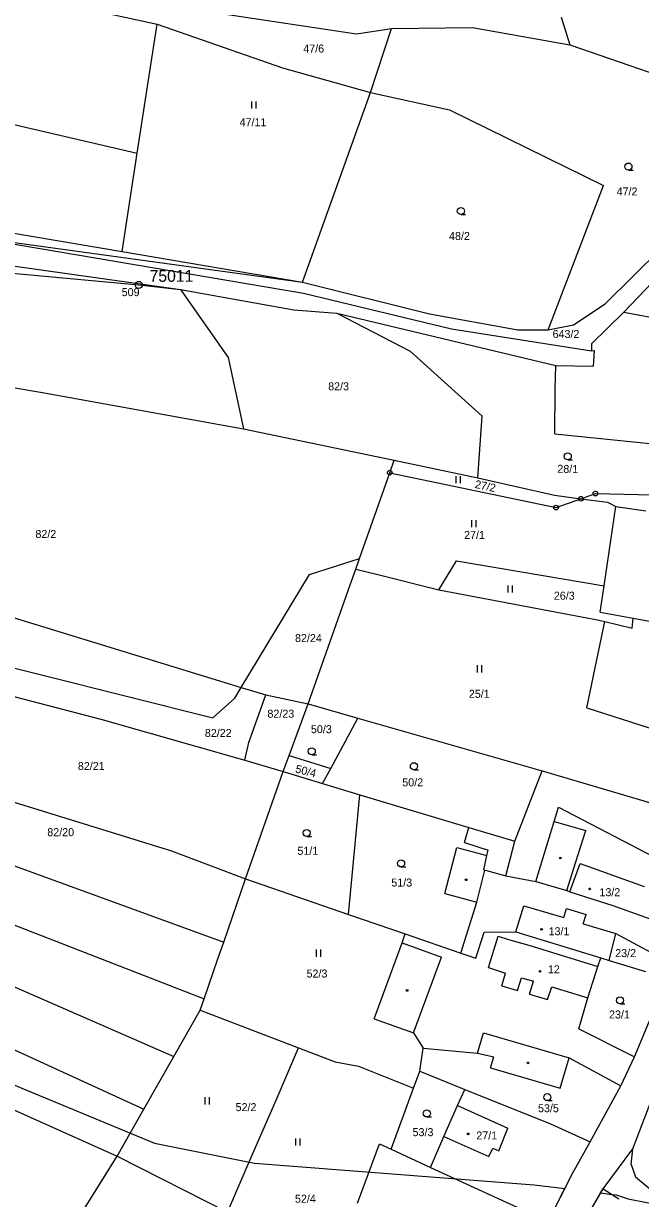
# Model space of a CAD drawing. Extents: x -743888 to -742027, y -1128394 to -1126768.
# Drawn here: x -743087.8 to -742956.8, y -1127574.7 to -1127325 of the extents above; entities that cross this region are included whole.
import ezdxf

# ---------------------------------------------------------------- set-up
doc = ezdxf.new("R2010")
doc.units = 0
for name, color, linetype in [('Vrstva 1', 7, 'Continuous'), ('Vrstva 17', 7, 'Continuous'), ('Vrstva 18', 7, 'Continuous'), ('Vrstva 19', 7, 'Continuous'), ('Vrstva 24', 7, 'Continuous'), ('Vrstva 25', 7, 'Continuous'), ('Vrstva 3', 7, 'Continuous'), ('Vrstva 37', 7, 'Continuous'), ('Vrstva 4', 7, 'Continuous'), ('Vrstva 52', 7, 'Continuous'), ('Vrstva 53', 7, 'Continuous'), ('Vrstva 6', 7, 'Continuous')]:
    doc.layers.add(name, color=color, linetype=linetype)

msp = doc.modelspace()

# ---------------------------------------------------------------- linework, layer by layer
at = {"layer": 'Vrstva 1'}
for p, q in [((-743010.06, -1127420.45), (-743009.13, -1127417.82)), ((-743016.5, -1127438.72), (-743010.06, -1127420.45)), ((-743010.06, -1127420.45), (-742974.74, -1127427.87)), ((-742975.09, -1127425.22), (-742969.45, -1127425.98)), ((-742974.74, -1127427.87), (-742969.45, -1127425.98)), ((-742969.45, -1127425.98), (-742966.36, -1127424.88)), ((-742969.45, -1127425.98), (-742963.79, -1127426.75)), ((-742966.36, -1127424.88), (-742929.36, -1127425.71))]:
    msp.add_line(p, q, dxfattribs=at)
for points in [[(-743048.7, -1127322.46), (-743017.08, -1127327.24)], [(-742973.63, -1127323.67), (-742971.84, -1127329.53)], [(-743017.08, -1127327.24), (-743009.69, -1127326.1)], [(-743014.16, -1127339.69), (-743009.69, -1127326.1)], [(-743009.69, -1127326.1), (-742992.5, -1127325.85)], [(-742992.5, -1127325.85), (-742971.84, -1127329.53)], [(-742971.84, -1127329.53), (-742954.93, -1127335.36)], [(-743028.55, -1127379.99), (-743014.16, -1127339.69)], [(-742976.38, -1127390.08), (-742964.65, -1127359.41)], [(-742964.3, -1127384.57), (-742946.62, -1127367.12)], [(-743147.34, -1127368.46), (-743054.48, -1127381.54)], [(-743100.68, -1127370.05), (-743028.55, -1127379.99)], [(-742960.31, -1127386.35), (-742945.39, -1127370.73)], [(-743054.48, -1127381.54), (-743044.4, -1127395.97)], [(-743054.48, -1127381.54), (-743030.41, -1127385.86)], [(-743028.55, -1127379.99), (-743001.6, -1127386.7)], [(-742971.06, -1127389.03), (-742964.3, -1127384.57)], [(-743030.41, -1127385.86), (-743021.3, -1127386.55)], [(-743021.3, -1127386.55), (-742974.81, -1127397.66)], [(-743001.6, -1127386.7), (-742982.84, -1127390.07)], [(-742967.2, -1127393.06), (-742960.31, -1127386.35)], [(-742960.31, -1127386.35), (-742951.24, -1127388.03)], [(-742976.38, -1127390.08), (-742971.06, -1127389.03)], [(-742982.84, -1127390.07), (-742976.38, -1127390.08)], [(-742967.2, -1127393.06), (-742967.2, -1127394.53)], [(-742967.2, -1127394.53), (-742966.54, -1127394.52)], [(-742966.76, -1127397.79), (-742966.54, -1127394.52)], [(-743044.4, -1127395.97), (-743041.1, -1127411.11)], [(-742974.95, -1127402.66), (-742974.81, -1127397.66)], [(-742974.81, -1127397.66), (-742966.76, -1127397.79)], [(-742975.01, -1127412.21), (-742974.95, -1127402.66)], [(-743041.1, -1127411.11), (-743009.13, -1127417.82)], [(-742975.01, -1127412.21), (-742949.94, -1127414.75)], [(-743009.13, -1127417.82), (-742991.33, -1127421.56)], [(-742991.33, -1127421.56), (-742975.09, -1127425.22)], [(-742963.79, -1127426.75), (-742962.06, -1127427.67)], [(-742964.54, -1127444.49), (-742962.06, -1127427.67)], [(-742962.06, -1127427.67), (-742955.66, -1127428.57)], [(-743017.29, -1127440.95), (-743016.5, -1127438.72)], [(-743018.47, -1127444.3), (-743017.29, -1127440.95)], [(-743017.29, -1127440.95), (-743012.61, -1127442.11)], [(-743012.61, -1127442.11), (-742999.6, -1127445.32)], [(-743027.39, -1127469.59), (-743018.47, -1127444.3)], [(-742965.34, -1127450.06), (-742964.54, -1127444.49)], [(-742999.6, -1127445.32), (-742965.61, -1127451.81)], [(-742965.61, -1127451.81), (-742964.4, -1127452.09)], [(-742965.34, -1127450.06), (-742958.39, -1127451.34)], [(-742958.39, -1127451.34), (-742942.2, -1127454.33)], [(-743031.43, -1127480.55), (-743027.39, -1127469.59)], [(-743027.39, -1127469.59), (-743016.81, -1127472.62)], [(-742968.23, -1127470.39), (-742947.25, -1127477.16)], [(-743022.6, -1127483.32), (-743016.81, -1127472.62)], [(-743016.81, -1127472.62), (-742977.71, -1127483.81)], [(-743032.69, -1127483.96), (-743031.43, -1127480.55)], [(-743040.66, -1127506.77), (-743032.69, -1127483.96)], [(-743032.69, -1127483.96), (-743024.31, -1127486.49)], [(-743024.31, -1127486.49), (-743022.6, -1127483.32)], [(-742983.49, -1127498.74), (-742977.71, -1127483.81)], [(-742977.71, -1127483.81), (-742954.21, -1127490.71)], [(-743024.31, -1127486.49), (-743016.42, -1127488.87)], [(-743016.42, -1127488.87), (-742993.26, -1127495.85)], [(-742975.14, -1127494.55), (-742974.21, -1127491.49)], [(-742974.21, -1127491.49), (-742943.52, -1127507.49)], [(-742979.03, -1127507.34), (-742975.14, -1127494.55)], [(-742993.26, -1127495.85), (-742983.49, -1127498.74)], [(-742985.43, -1127506.13), (-742983.49, -1127498.74)], [(-742998.35, -1127509.89), (-742995.84, -1127500.07)], [(-742995.84, -1127500.07), (-742989.41, -1127501.75)], [(-742990.08, -1127504.83), (-742989.41, -1127501.75)], [(-743045.31, -1127520.19), (-743040.66, -1127506.77)], [(-743040.66, -1127506.77), (-743018.83, -1127514.29)], [(-742990.08, -1127504.83), (-742989.89, -1127504.88)], [(-742989.89, -1127504.88), (-742989.51, -1127504.99)], [(-742989.51, -1127504.99), (-742985.43, -1127506.13)], [(-742985.43, -1127506.13), (-742979.03, -1127507.34)], [(-742979.03, -1127507.34), (-742972.41, -1127509.22)], [(-742972.41, -1127509.22), (-742971.81, -1127509.49)], [(-742971.81, -1127509.49), (-742962.69, -1127512.44)], [(-742998.35, -1127509.89), (-742991.56, -1127511.71)], [(-742994.94, -1127522.52), (-742991.56, -1127511.71)], [(-743018.83, -1127514.29), (-743006.77, -1127518.44)], [(-742962.69, -1127512.44), (-742949.22, -1127517.23)], [(-743007.45, -1127520.31), (-743006.77, -1127518.44)], [(-743006.77, -1127518.44), (-742994.94, -1127522.52)], [(-742991.77, -1127523.61), (-742989.99, -1127518.04)], [(-742983.25, -1127518.03), (-742965.23, -1127523.55)], [(-742963.44, -1127524.1), (-742962.06, -1127518.33)], [(-742962.06, -1127518.33), (-742949.93, -1127524.86)], [(-743046.55, -1127523.76), (-743045.31, -1127520.19)], [(-743013.35, -1127536.47), (-743007.45, -1127520.31)], [(-743049.5, -1127532.27), (-743046.55, -1127523.76)], [(-742994.94, -1127522.52), (-742991.77, -1127523.61)], [(-742965.83, -1127525.39), (-742965.23, -1127523.55)], [(-742965.23, -1127523.55), (-742963.44, -1127524.1)], [(-742968.01, -1127532.03), (-742965.83, -1127525.39)], [(-742969.92, -1127538.58), (-742968.01, -1127532.03)], [(-742958.07, -1127544.59), (-742952.01, -1127529.96)], [(-743050.32, -1127534.62), (-743049.5, -1127532.27)], [(-743055.93, -1127544.5), (-743050.32, -1127534.62)], [(-743050.32, -1127534.62), (-743029.41, -1127542.64)], [(-743013.35, -1127536.47), (-743005, -1127539.46)], [(-743005, -1127539.46), (-743002.99, -1127542.69)], [(-742969.92, -1127538.58), (-742958.07, -1127544.59)], [(-743062.27, -1127555.66), (-743055.93, -1127544.5)], [(-743034.2, -1127553.73), (-743029.41, -1127542.64)], [(-743029.41, -1127542.64), (-743021.68, -1127545.63)], [(-743003.69, -1127547.61), (-743002.99, -1127542.69)], [(-743002.99, -1127542.69), (-742991.4, -1127543.81)], [(-742991.4, -1127543.81), (-742987.95, -1127544.57)], [(-743021.68, -1127545.63), (-743016.66, -1127546.56)], [(-743016.66, -1127546.56), (-743005.01, -1127551.2)], [(-742988.63, -1127546.87), (-742987.95, -1127544.57)], [(-742988.63, -1127546.87), (-742973.89, -1127551.23)], [(-742973.89, -1127551.23), (-742971.94, -1127544.76)], [(-742971.94, -1127544.76), (-742960.97, -1127550.69)], [(-742960.97, -1127550.69), (-742958.07, -1127544.59)], [(-743005.01, -1127551.2), (-743003.69, -1127547.61)], [(-743003.69, -1127547.61), (-742994.1, -1127551.47)], [(-743009.74, -1127564.2), (-743005.01, -1127551.2)], [(-742995.64, -1127554.9), (-742994.1, -1127551.47)], [(-742994.1, -1127551.47), (-742975.9, -1127558.78)], [(-742967.51, -1127562.65), (-742960.97, -1127550.69)], [(-743039.4, -1127565.75), (-743034.2, -1127553.73)], [(-742958.43, -1127564.08), (-742954.72, -1127554.49)], [(-743067.95, -1127565.66), (-743062.27, -1127555.66)], [(-742998.58, -1127561.51), (-742995.64, -1127554.9)], [(-742975.9, -1127558.78), (-742967.51, -1127562.65)], [(-743001.38, -1127568.05), (-742998.58, -1127561.51)], [(-743016.9, -1127575.68), (-743012.24, -1127563.05)], [(-743012.24, -1127563.05), (-743009.74, -1127564.2)], [(-743009.74, -1127564.2), (-743001.38, -1127568.05)], [(-742971.19, -1127569.17), (-742967.51, -1127562.65)], [(-742964.75, -1127572.6), (-742958.43, -1127564.08)], [(-742958.76, -1127567.42), (-742958.43, -1127564.08)], [(-743072.64, -1127573.17), (-743067.95, -1127565.66)], [(-743067.95, -1127565.66), (-743044.5, -1127577.53)], [(-743044.5, -1127577.53), (-743039.4, -1127565.75)], [(-743001.38, -1127568.05), (-742979.47, -1127578.16)], [(-742976.43, -1127579.56), (-742971.19, -1127569.17)], [(-742958.76, -1127567.42), (-742957.84, -1127570.04)], [(-742957.84, -1127570.04), (-742953.72, -1127573.43)], [(-743082.43, -1127588.87), (-743072.64, -1127573.17)], [(-742970.21, -1127581.92), (-742964.75, -1127572.6)], [(-742964.75, -1127572.6), (-742961.39, -1127574.71)]]:
    msp.add_lwpolyline(points, dxfattribs=at)
at = {"layer": 'Vrstva 24'}
for p, q in [((-743063.41, -1127380.56), (-743063.31, -1127380.56)), ((-743010.11, -1127420.45), (-743010.01, -1127420.45)), ((-742969.5, -1127425.98), (-742969.4, -1127425.98)), ((-742966.41, -1127424.88), (-742966.31, -1127424.88)), ((-742974.79, -1127427.87), (-742974.69, -1127427.87))]:
    msp.add_line(p, q, dxfattribs=at)
for centre, radius in [((-743063.36, -1127380.56), 0.756), ((-743010.06, -1127420.45), 0.499), ((-742966.36, -1127424.88), 0.499), ((-742969.45, -1127425.98), 0.499), ((-742974.74, -1127427.87), 0.499)]:
    msp.add_circle(centre, radius, dxfattribs=at)
at = {"layer": 'Vrstva 25'}
for p, q in [((-743039.43, -1127341.57), (-743039.43, -1127343.07)), ((-743038.43, -1127343.07), (-743038.43, -1127341.57)), ((-742959.36, -1127356.16), (-742958.36, -1127356.16)), ((-742994.95, -1127365.62), (-742993.95, -1127365.62)), ((-742972.24, -1127417.73), (-742971.24, -1127417.73)), ((-742996, -1127421.2), (-742996, -1127422.7)), ((-742995, -1127422.7), (-742995, -1127421.2)), ((-742992.72, -1127430.55), (-742992.72, -1127432.05)), ((-742991.72, -1127432.05), (-742991.72, -1127430.55)), ((-742984.95, -1127444.4), (-742984.95, -1127445.9)), ((-742983.95, -1127445.9), (-742983.95, -1127444.4)), ((-742991.51, -1127461.38), (-742991.51, -1127462.88)), ((-742990.51, -1127462.88), (-742990.51, -1127461.38)), ((-743026.61, -1127480.4), (-743025.61, -1127480.4)), ((-743004.92, -1127483.57), (-743003.92, -1127483.57)), ((-743027.69, -1127497.75), (-743026.69, -1127497.75)), ((-743007.64, -1127504.22), (-743006.64, -1127504.22)), ((-743025.67, -1127521.78), (-743025.67, -1127523.28)), ((-743024.67, -1127523.28), (-743024.67, -1127521.78)), ((-742961.15, -1127533.31), (-742960.15, -1127533.31)), ((-743049.36, -1127553.15), (-743049.36, -1127554.65)), ((-743048.36, -1127554.65), (-743048.36, -1127553.15)), ((-742976.58, -1127553.86), (-742975.58, -1127553.86)), ((-743002.18, -1127557.34), (-743001.18, -1127557.34)), ((-743030.06, -1127561.93), (-743030.06, -1127563.43)), ((-743029.06, -1127563.43), (-743029.06, -1127561.93))]:
    msp.add_line(p, q, dxfattribs=at)
for centre, radius in [((-742959.36, -1127355.41), 0.75), ((-742994.95, -1127364.87), 0.75), ((-742972.24, -1127416.98), 0.75), ((-743026.61, -1127479.65), 0.75), ((-743004.92, -1127482.82), 0.75), ((-743027.69, -1127497), 0.75), ((-743007.64, -1127503.47), 0.75), ((-742973.84, -1127502.33), 0.175), ((-742993.83, -1127506.94), 0.175), ((-742967.6, -1127508.88), 0.175), ((-742977.81, -1127517.48), 0.175), ((-742978.13, -1127526.39), 0.175), ((-743006.37, -1127530.46), 0.175), ((-742961.15, -1127532.56), 0.75), ((-742980.7, -1127545.84), 0.175), ((-742976.58, -1127553.11), 0.75), ((-743002.18, -1127556.59), 0.75), ((-742993.39, -1127560.92), 0.175)]:
    msp.add_circle(centre, radius, dxfattribs=at)
at = {"layer": 'Vrstva 3'}
for points in [[(-742971.81, -1127509.49), (-742969.62, -1127503.47)], [(-742969.62, -1127503.47), (-742956.03, -1127508.38)], [(-742971.81, -1127509.49), (-742962.69, -1127512.44)], [(-742983.25, -1127518.03), (-742981.6, -1127512.47)], [(-742981.6, -1127512.47), (-742973.1, -1127514.99)], [(-742973.1, -1127514.99), (-742972.53, -1127513.06)], [(-742972.53, -1127513.06), (-742968.35, -1127514.3)], [(-742968.94, -1127516.27), (-742968.35, -1127514.3)], [(-742962.69, -1127512.44), (-742949.22, -1127517.23)], [(-742968.94, -1127516.27), (-742962.06, -1127518.33)], [(-742989.07, -1127525.61), (-742987.02, -1127518.91)], [(-742987.02, -1127518.91), (-742984.85, -1127519.61)], [(-742983.25, -1127518.03), (-742965.23, -1127523.55)], [(-742963.44, -1127524.1), (-742962.06, -1127518.33)], [(-742984.85, -1127519.61), (-742980.49, -1127520.84)], [(-742980.49, -1127520.84), (-742965.83, -1127525.39)], [(-742965.23, -1127523.55), (-742963.44, -1127524.1)], [(-742989.07, -1127525.61), (-742985.46, -1127526.79)], [(-742986.28, -1127529.44), (-742985.46, -1127526.79)], [(-742968.01, -1127532.03), (-742965.83, -1127525.39)], [(-742986.28, -1127529.44), (-742982.9, -1127530.47)], [(-742982.9, -1127530.47), (-742982.08, -1127527.77)], [(-742982.08, -1127527.77), (-742979.51, -1127528.51)], [(-742980.35, -1127531.26), (-742979.51, -1127528.51)], [(-742980.35, -1127531.26), (-742976.56, -1127532.4)], [(-742976.56, -1127532.4), (-742975.66, -1127529.7)], [(-742975.66, -1127529.7), (-742968.01, -1127532.03)], [(-742998.58, -1127561.51), (-742995.64, -1127554.9)], [(-742995.64, -1127554.9), (-742984.94, -1127559.69)], [(-742998.58, -1127561.51), (-742988.98, -1127565.74)], [(-742986.89, -1127564.52), (-742984.94, -1127559.69)], [(-742988.98, -1127565.74), (-742988.19, -1127563.94)], [(-742988.19, -1127563.94), (-742986.89, -1127564.52)]]:
    msp.add_lwpolyline(points, dxfattribs=at)
at = {"layer": 'Vrstva 37'}
for centre in [(-742967.6, -1127508.88), (-742977.81, -1127517.48), (-742978.13, -1127526.39), (-742993.39, -1127560.92)]:
    msp.add_circle(centre, 0.175, dxfattribs=at)
at = {"layer": 'Vrstva 4'}
for points in [[(-742975.14, -1127494.55), (-742968.39, -1127496.47)], [(-742994.2, -1127499.03), (-742993.26, -1127495.85)], [(-742970.5, -1127503.16), (-742968.39, -1127496.47)], [(-742994.2, -1127499.03), (-742989.17, -1127500.66)], [(-742989.41, -1127501.75), (-742989.17, -1127500.66)], [(-742972.41, -1127509.22), (-742970.5, -1127503.16)], [(-742971.81, -1127509.49), (-742969.62, -1127503.47)], [(-742969.62, -1127503.47), (-742956.03, -1127508.38)], [(-742991.56, -1127511.71), (-742989.89, -1127504.88)], [(-742983.25, -1127518.03), (-742981.6, -1127512.47)], [(-742981.6, -1127512.47), (-742973.1, -1127514.99)], [(-742973.1, -1127514.99), (-742972.53, -1127513.06)], [(-742972.53, -1127513.06), (-742968.35, -1127514.3)], [(-742968.94, -1127516.27), (-742968.35, -1127514.3)], [(-742968.94, -1127516.27), (-742962.06, -1127518.33)], [(-742989.07, -1127525.61), (-742987.02, -1127518.91)], [(-742987.02, -1127518.91), (-742984.85, -1127519.61)], [(-743007.45, -1127520.31), (-742999.03, -1127523.38)], [(-742984.85, -1127519.61), (-742980.49, -1127520.84)], [(-742980.49, -1127520.84), (-742965.83, -1127525.39)], [(-743005, -1127539.46), (-742999.03, -1127523.38)], [(-742989.07, -1127525.61), (-742985.46, -1127526.79)], [(-742986.28, -1127529.44), (-742985.46, -1127526.79)], [(-742986.28, -1127529.44), (-742982.9, -1127530.47)], [(-742982.9, -1127530.47), (-742982.08, -1127527.77)], [(-742982.08, -1127527.77), (-742979.51, -1127528.51)], [(-742980.35, -1127531.26), (-742979.51, -1127528.51)], [(-742980.35, -1127531.26), (-742976.56, -1127532.4)], [(-742976.56, -1127532.4), (-742975.66, -1127529.7)], [(-742975.66, -1127529.7), (-742968.01, -1127532.03)], [(-742991.4, -1127543.81), (-742990.15, -1127539.46)], [(-742990.15, -1127539.46), (-742971.94, -1127544.76)], [(-742995.64, -1127554.9), (-742984.94, -1127559.69)], [(-742998.58, -1127561.51), (-742988.98, -1127565.74)], [(-742986.89, -1127564.52), (-742984.94, -1127559.69)], [(-742988.98, -1127565.74), (-742988.19, -1127563.94)], [(-742988.19, -1127563.94), (-742986.89, -1127564.52)]]:
    msp.add_lwpolyline(points, dxfattribs=at)
at = {"layer": 'Vrstva 52'}
for points in [[(-742972.89, -1127572.54), (-742971.19, -1127569.17), (-742967.51, -1127562.65), (-742960.97, -1127550.69), (-742958.07, -1127544.59), (-742952.01, -1127529.96), (-742951.87, -1127529.63), (-742949.93, -1127524.86), (-742947.48, -1127518.45), (-742943.52, -1127507.49), (-742939.27, -1127495.28), (-742928.77, -1127471.57), (-742930.03, -1127470.75), (-742926.01, -1127462.54), (-742919.56, -1127450.77), (-742911.88, -1127437.64), (-742907.65, -1127433.29), (-742900.6, -1127419.3), (-742892.14, -1127404.73), (-742890.15, -1127399.92)], [(-742965.26, -1127573.48), (-742964.75, -1127572.6), (-742958.43, -1127564.08), (-742954.72, -1127554.49), (-742950.97, -1127547.61), (-742944.28, -1127528.98), (-742929.86, -1127490.53), (-742926.08, -1127481.57), (-742925.07, -1127479.17), (-742918.99, -1127466.07), (-742914.39, -1127456.16), (-742910.36, -1127448.54), (-742907.43, -1127444.81), (-742902.44, -1127441.06), (-742891.64, -1127420.53), (-742883.68, -1127406.25)], [(-743096.94, -1127547.63), (-743060, -1127562.88), (-743038.81, -1127567.13), (-742979.38, -1127571.75), (-742972.89, -1127572.54)], [(-743014.19, -1127643.46), (-743006.21, -1127631.58), (-743002.72, -1127626.56), (-742999.93, -1127620.98), (-743000.05, -1127620.45), (-742996.62, -1127614.4), (-742993.07, -1127607.9), (-742991.6, -1127605.04), (-742983.9, -1127588.07), (-742980.12, -1127580.33), (-742979.47, -1127578.16), (-742976.43, -1127579.56), (-742972.89, -1127572.54)], [(-742999.9, -1127643.94), (-742990.11, -1127623.65), (-742984.29, -1127611.5), (-742984.97, -1127610.98), (-742978.95, -1127598.97), (-742974.2, -1127589.77), (-742973.05, -1127587.2), (-742970.21, -1127581.92), (-742965.26, -1127573.48)], [(-742965.26, -1127573.48), (-742962.89, -1127573.77), (-742962, -1127573.88), (-742959.44, -1127574.75), (-742946.43, -1127577.24), (-742935.31, -1127579.38), (-742933.19, -1127580.25), (-742923.81, -1127581.5), (-742895, -1127588.25), (-742870.38, -1127595.5), (-742826.25, -1127613.38), (-742782.56, -1127629.88), (-742777.06, -1127632.88), (-742760.94, -1127638.75), (-742741, -1127643.5)]]:
    msp.add_lwpolyline(points, dxfattribs=at)
at = {"layer": 'Vrstva 6'}
for points in [[(-743086.21, -1127319.28), (-743059.46, -1127325.17)], [(-743063.68, -1127352.59), (-743059.46, -1127325.17)], [(-743059.46, -1127325.17), (-743032.86, -1127334.46)], [(-743140.7, -1127334.62), (-743063.68, -1127352.59)], [(-743032.86, -1127334.46), (-743014.16, -1127339.69)], [(-743014.16, -1127339.69), (-742997.35, -1127343.38)], [(-742997.35, -1127343.38), (-742964.65, -1127359.41)], [(-743066.9, -1127373.47), (-743063.68, -1127352.59)], [(-743161.95, -1127357.36), (-743066.9, -1127373.47)], [(-743100.68, -1127370.05), (-743028.35, -1127382.31)], [(-743066.9, -1127373.47), (-743028.55, -1127379.99)], [(-743112.56, -1127376.02), (-743063.36, -1127380.56)], [(-743063.36, -1127380.56), (-743054.48, -1127381.54)], [(-743028.35, -1127382.31), (-742996.94, -1127389.89)], [(-743021.3, -1127386.55), (-743005.74, -1127394.62)], [(-743167.67, -1127389.27), (-743084.2, -1127403.32)], [(-742996.94, -1127389.89), (-742967.2, -1127394.53)], [(-743005.74, -1127394.62), (-742990.42, -1127408.45)], [(-743084.2, -1127403.32), (-743041.1, -1127411.11)], [(-742991.33, -1127421.56), (-742990.42, -1127408.45)], [(-743027.12, -1127442.06), (-743016.5, -1127438.72)], [(-742999.6, -1127445.32), (-742995.91, -1127439.17)], [(-742995.91, -1127439.17), (-742964.54, -1127444.49)], [(-743041.59, -1127466.09), (-743027.12, -1127442.06)], [(-743108.99, -1127445.38), (-743041.59, -1127466.09)], [(-743155.92, -1127450.8), (-743071.4, -1127472.85)], [(-742968.23, -1127470.39), (-742964.4, -1127452.09)], [(-742964.4, -1127452.09), (-742958.54, -1127453.46)], [(-742958.54, -1127453.46), (-742958.39, -1127451.34)], [(-743119.92, -1127454.41), (-743047.66, -1127472.53)], [(-743042.97, -1127468.39), (-743041.59, -1127466.09)], [(-743041.59, -1127466.09), (-743036.38, -1127467.62)], [(-743047.66, -1127472.53), (-743042.97, -1127468.39)], [(-743039.98, -1127477.77), (-743036.38, -1127467.62)], [(-743036.38, -1127467.62), (-743027.39, -1127469.59)], [(-743071.4, -1127472.85), (-743040.81, -1127481.55)], [(-743133.85, -1127476.88), (-743056.44, -1127500.82)], [(-743040.81, -1127481.55), (-743039.98, -1127477.77)], [(-743040.81, -1127481.55), (-743032.69, -1127483.96)], [(-743031.43, -1127480.55), (-743022.6, -1127483.32)], [(-743018.83, -1127514.29), (-743016.42, -1127488.87)], [(-743155.28, -1127491.09), (-743049.5, -1127532.27)], [(-743164.36, -1127497.11), (-743055.93, -1127544.5)], [(-743104.96, -1127498.48), (-743045.31, -1127520.19)], [(-743056.44, -1127500.82), (-743040.66, -1127506.77)], [(-743157.93, -1127511.82), (-743062.27, -1127555.66)], [(-742989.99, -1127518.04), (-742983.25, -1127518.03)], [(-742963.44, -1127524.1), (-742955.76, -1127526.44)], [(-743113.85, -1127545.15), (-743067.95, -1127565.66)]]:
    msp.add_lwpolyline(points, dxfattribs=at)

# ---------------------------------------------------------------- texts
at = {"layer": 'Vrstva 17'}
msp.add_text('509', height=1.7, dxfattribs=at).set_placement((-743066.98, -1127382.94))
at = {"layer": 'Vrstva 18'}
for s, p in [('47/6', (-743028.42, -1127331.2)), ('47/11', (-743041.94, -1127346.84)), ('47/2', (-742961.87, -1127361.56)), ('48/2', (-742997.46, -1127371.02)), ('643/2', (-742975.47, -1127391.84)), ('82/3', (-743023.13, -1127402.95)), ('82/2', (-743085.3, -1127434.33)), ('27/1', (-742994.26, -1127434.53)), ('26/3', (-742975.2, -1127447.44)), ('82/24', (-743030.17, -1127456.44)), ('25/1', (-742993.25, -1127468.28)), ('82/23', (-743036.03, -1127472.51)), ('50/3', (-743026.79, -1127475.8)), ('82/22', (-743049.32, -1127476.6)), ('82/21', (-743076.29, -1127483.62)), ('50/2', (-743007.39, -1127487.09)), ('82/20', (-743082.78, -1127497.68)), ('51/1', (-743029.66, -1127501.64)), ('51/3', (-743009.72, -1127508.38)), ('23/2', (-742962.17, -1127523.36)), ('52/3', (-743027.72, -1127527.71)), ('23/1', (-742963.48, -1127536.41)), ('52/2', (-743042.79, -1127556.09)), ('53/5', (-742978.56, -1127556.33)), ('53/3', (-743005.2, -1127561.41)), ('52/4', (-743030.18, -1127575.55))]:
    msp.add_text(s, height=1.7, dxfattribs=at).set_placement(p)
for s, rotation, p in [('28/1', 358.7149, (-742974.48, -1127420.46)), ('27/2', 348.134, (-742992.09, -1127423.67)), ('50/4', 345.4701, (-743030.22, -1127484.11))]:
    msp.add_text(s, height=1.7, rotation=rotation, dxfattribs=at).set_placement(p)
at = {"layer": 'Vrstva 19'}
for s, p in [('13/2', (-742965.52, -1127510.43)), ('13/1', (-742976.32, -1127518.73)), ('12', (-742976.46, -1127526.81)), ('27/1', (-742991.67, -1127562.12))]:
    msp.add_text(s, height=1.7, dxfattribs=at).set_placement(p)
at = {"layer": 'Vrstva 53'}
msp.add_text('75011', height=2.5, dxfattribs=at).set_placement((-743061.06, -1127379.9))

doc.saveas('drawing.dxf')
